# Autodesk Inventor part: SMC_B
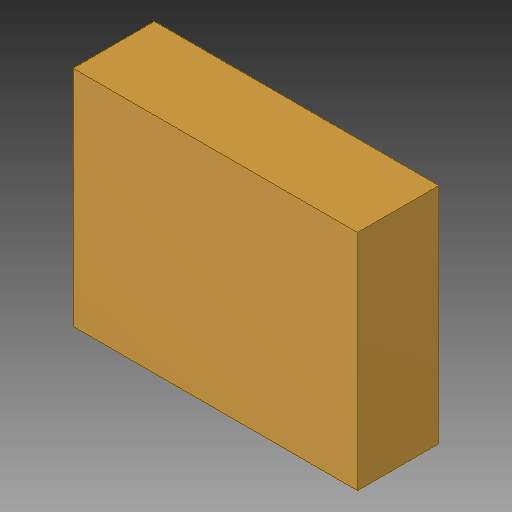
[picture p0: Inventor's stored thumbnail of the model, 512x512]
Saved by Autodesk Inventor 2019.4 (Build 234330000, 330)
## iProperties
Created: 2019-11
Part Number: SMC_B
Material: Generic
Document SubType Name: Modeling
Designer: Willist
Density: 1 g/cm^3
Appearance: SMC_B, SMC_B
Author: Willist
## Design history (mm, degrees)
sketch "SMC_B, SMC_B_6"
  geometry: L1 (-1.75, 1.401)-(1.75, 1.401); L2 (1.75, 1.401)-(1.75, -1.35); L3 (1.75, -1.35)-(-1.75, -1.35); L4 (-1.75, -1.35)-(-1.75, 1.401)
  constraints: 8 end point
extrude "Extrusion1" join sketch "SMC_B, SMC_B_6" distance "d0" = 1; taper "d1" = 0 deg
body "Solid1"
